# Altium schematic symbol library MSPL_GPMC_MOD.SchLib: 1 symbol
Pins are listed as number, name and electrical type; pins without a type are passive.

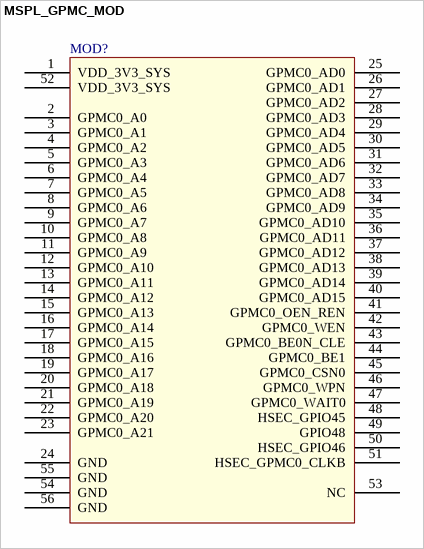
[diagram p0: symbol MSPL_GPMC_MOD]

## MSPL_GPMC_MOD
designator MOD?
footprint MSPL_GPMC_MOD
pins: 1 VDD_3V3_SYS, 2 GPMC0_A0, 3 GPMC0_A1, 4 GPMC0_A2, 5 GPMC0_A3, 6 GPMC0_A4, 7 GPMC0_A5, 8 GPMC0_A6, 9 GPMC0_A7, 10 GPMC0_A8, 11 GPMC0_A9, 12 GPMC0_A10, 13 GPMC0_A11, 14 GPMC0_A12, 15 GPMC0_A13, 16 GPMC0_A14, 17 GPMC0_A15, 18 GPMC0_A16, 19 GPMC0_A17, 20 GPMC0_A18, 21 GPMC0_A19, 22 GPMC0_A20, 23 GPMC0_A21, 24 GND (power), 25 GPMC0_AD0, 26 GPMC0_AD1, 27 GPMC0_AD2, 28 GPMC0_AD3, 29 GPMC0_AD4, 30 GPMC0_AD5, 31 GPMC0_AD6, 32 GPMC0_AD7, 33 GPMC0_AD8, 34 GPMC0_AD9, 35 GPMC0_AD10, 36 GPMC0_AD11, 37 GPMC0_AD12, 38 GPMC0_AD13, 39 GPMC0_AD14, 40 GPMC0_AD15, 41 GPMC0_OEN_REN, 42 GPMC0_WEN, 43 GPMC0_BE0N_CLE, 44 GPMC0_BE1, 45 GPMC0_CSN0, 46 GPMC0_WPN, 47 GPMC0_WAIT0, 48 HSEC_GPIO45, 49 GPIO48, 50 HSEC_GPIO46, 51 HSEC_GPMC0_CLKB, 52 VDD_3V3_SYS, 53 NC, 54 GND, 55 GND, 56 GND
